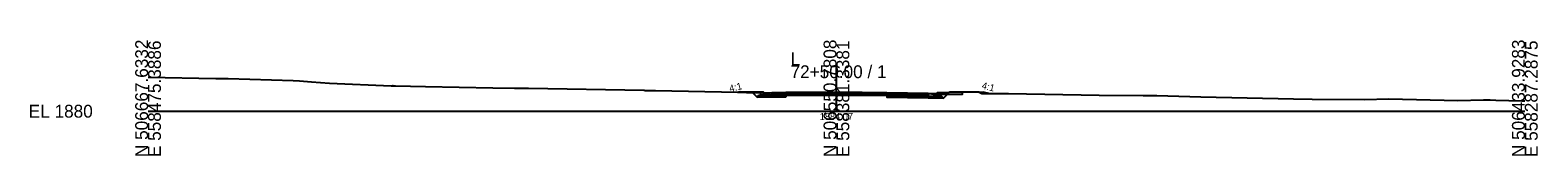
# Model space of a CAD drawing. Extents: x -26 to 4603, y -10 to 4703.
# Drawn here: x 2974.3 to 3302.8, y 1045.3 to 1070.4 of the extents above; entities that cross this region are included whole.
import ezdxf

# ---------------------------------------------------------------- set-up
doc = ezdxf.new("R2010")
doc.units = 0
for name, color, linetype in [('Default', 7, 'Continuous'), ('Exist Cross Section Cell', 7, 'Continuous'), ('Exist XS Ground Line', 7, 'Continuous'), ('Prop CMT Pvmt Course 1', 7, 'Continuous'), ('Prop CMT Pvmt Course 2', 7, 'Continuous'), ('Prop CMT Pvmt Course 3', 7, 'Continuous'), ('Prop CMT Pvmt Milling', 7, 'Continuous'), ('Prop CMT Shear Line', 7, 'Continuous'), ('Prop CMT Shld Paved Course 2', 7, 'Continuous'), ('Prop CMT Shld Paved Course 3', 7, 'Continuous'), ('Prop CMT Subgrade Earthwork', 7, 'Continuous'), ('Prop Conc 4in Sidewalk', 7, 'Continuous'), ('Prop Conc Curb and Gutter', 7, 'Continuous'), ('Prop Corridor Mesh Bottom', 7, 'Continuous'), ('Prop XS Finish Grade', 7, 'Continuous'), ('Prop XS Label Text', 7, 'Continuous'), ('Prop XS SS Elevation Text', 7, 'Continuous'), ('Scratch_Level_9', 7, 'Continuous')]:
    doc.layers.add(name, color=color, linetype=linetype)

msp = doc.modelspace()

# ---------------------------------------------------------------- linework, layer by layer
at = {"layer": 'Exist Cross Section Cell'}
for p, q in [((3150, 1055), (3150, 1065)), ((3000, 1055), (3150, 1055)), ((3150, 1055), (3300, 1055))]:
    msp.add_line(p, q, dxfattribs=at)
at = {"layer": 'Exist XS Ground Line'}
msp.add_lwpolyline([(3000, 1062.38), (3014.79, 1062.14), (3017.48, 1062.1), (3031.64, 1061.69), (3033, 1061.61), (3035.63, 1061.38), (3039.52, 1061.14), (3053, 1060.5), (3053.15, 1060.5), (3053.23, 1060.5), (3053.31, 1060.59), (3053.37, 1060.51), (3053.94, 1060.52), (3060.45, 1060.4), (3075.13, 1060.09), (3079.87, 1060.03), (3082.93, 1059.99), (3108.13, 1059.55), (3108.3, 1059.54), (3110.54, 1059.52), (3128.52, 1059.16), (3130.43, 1059.11), (3134.19, 1058.99), (3148.79, 1059.08), (3150.35, 1059.06), (3155.58, 1059.05), (3160.82, 1058.99), (3165.7, 1058.93), (3172.64, 1058.83), (3173.96, 1058.78), (3174.05, 1058.77), (3174.66, 1059.16), (3174.71, 1059.19), (3174.86, 1059.2), (3176.9, 1059.19), (3180.72, 1059.21), (3181.03, 1059.21), (3181.07, 1059.18), (3181.67, 1058.84), (3182.94, 1058.85), (3183.04, 1058.85), (3183.79, 1058.86), (3187.48, 1058.86), (3207.27, 1058.49), (3216.87, 1058.44), (3219.76, 1058.39), (3219.81, 1058.39), (3229.42, 1058.14), (3249.63, 1057.69), (3253.66, 1057.61), (3265.1, 1057.55), (3270.37, 1057.66), (3285.38, 1057.36), (3291.02, 1057.49), (3292.42, 1057.46), (3293.68, 1057.43), (3299.37, 1057.26), (3300, 1057.24)], dxfattribs=at)
at = {"layer": 'Prop CMT Pvmt Course 1'}
for points in [[(3136, 1059.1), (3139, 1059.1), (3139, 1058.85), (3139, 1058.85), (3136, 1058.85), (3136, 1058.85), (3136, 1058.85), (3136, 1059.1), (3136, 1059.1)], [(3150, 1059.1), (3148.79, 1059.08), (3148.79, 1059.08), (3139, 1059.1), (3139, 1059.1), (3139, 1058.85), (3139, 1058.85), (3139, 1058.85), (3148.79, 1058.83), (3148.79, 1058.83), (3150, 1058.85), (3150, 1058.85), (3150, 1058.85), (3150, 1059.1), (3150, 1059.1)], [(3161, 1058.98), (3150.35, 1059.1), (3150, 1059.1), (3150, 1058.85), (3150, 1058.85), (3150.35, 1058.85), (3161, 1058.73), (3161, 1058.73), (3161, 1058.98)], [(3161, 1058.98), (3161, 1058.98), (3161, 1058.73), (3161, 1058.73), (3161, 1058.73), (3169.96, 1058.62), (3169.96, 1058.62), (3169.96, 1058.87), (3161, 1058.98)]]:
    msp.add_lwpolyline(points, dxfattribs=at)
at = {"layer": 'Prop CMT Pvmt Course 2'}
for points in [[(3136, 1058.85), (3139, 1058.85), (3139, 1058.52), (3139, 1058.52), (3136, 1058.52), (3136, 1058.52), (3136, 1058.52), (3136, 1058.85), (3136, 1058.85)], [(3161, 1058.73), (3161, 1058.73), (3161, 1058.4), (3161, 1058.4), (3161, 1058.4), (3169.96, 1058.29), (3169.96, 1058.29), (3169.96, 1058.62), (3161, 1058.73)]]:
    msp.add_lwpolyline(points, dxfattribs=at)
at = {"layer": 'Prop CMT Pvmt Course 3'}
for points in [[(3136, 1058.52), (3139, 1058.52), (3139, 1058.15), (3139, 1058.15), (3136, 1058.15), (3136, 1058.15), (3136, 1058.15), (3136, 1058.52), (3136, 1058.52)], [(3161, 1058.4), (3161, 1058.4), (3161, 1058.03), (3161, 1058.03), (3161, 1058.03), (3169.96, 1057.91), (3169.96, 1057.91), (3169.96, 1058.29), (3161, 1058.47)], [(3169.96, 1058.29), (3169.96, 1058.29), (3169.96, 1057.91), (3169.96, 1057.91), (3169.96, 1057.91), (3173.35, 1057.84), (3173.35, 1057.84), (3172.97, 1058.23), (3169.96, 1058.29)]]:
    msp.add_lwpolyline(points, dxfattribs=at)
at = {"layer": 'Prop CMT Pvmt Milling'}
for points in [[(3150, 1059.07), (3148.79, 1059.08), (3148.79, 1059.08), (3139, 1059.02), (3139, 1059.02), (3139, 1058.98), (3139, 1058.98), (3139, 1058.98), (3148.79, 1058.96), (3148.79, 1058.96), (3150, 1058.98), (3150, 1058.98), (3150, 1058.98), (3150, 1059.07), (3150, 1059.07)], [(3161, 1058.98), (3155.58, 1059.05), (3150.35, 1059.06), (3150, 1059.07), (3150, 1058.98), (3150, 1058.98), (3150.35, 1058.97), (3161, 1058.86), (3161, 1058.86), (3161, 1058.86), (3161, 1058.86), (3161, 1058.98), (3161, 1058.98), (3161, 1058.98)]]:
    msp.add_lwpolyline(points, dxfattribs=at)
at = {"layer": 'Prop CMT Shld Paved Course 2'}
for points in [[(3150, 1058.85), (3148.79, 1058.83), (3148.79, 1058.83), (3139, 1058.85), (3139, 1058.85), (3139, 1058.52), (3139, 1058.52), (3139, 1058.52), (3148.79, 1058.5), (3148.79, 1058.5), (3150, 1058.52), (3150, 1058.52), (3150, 1058.52), (3150, 1058.85), (3150, 1058.85)], [(3161, 1058.73), (3150.35, 1058.85), (3150, 1058.85), (3150, 1058.52), (3150, 1058.52), (3150.35, 1058.51), (3161, 1058.4), (3161, 1058.4), (3161, 1058.4), (3161, 1058.4), (3161, 1058.73), (3161, 1058.73), (3161, 1058.73)]]:
    msp.add_lwpolyline(points, dxfattribs=at)
at = {"layer": 'Prop CMT Shld Paved Course 3'}
msp.add_lwpolyline([(3133, 1058.46), (3136, 1058.52), (3136, 1058.15), (3136, 1058.15), (3132.7, 1058.08), (3132.7, 1058.08), (3132.7, 1058.08), (3133, 1058.46), (3133, 1058.46)], dxfattribs=at)
at = {"layer": 'Prop CMT Subgrade Earthwork'}
msp.add_line((3132.7, 1058.08), (3136, 1058.15), dxfattribs=at)
for points in [[(3131.54, 1059.24), (3132.7, 1058.08), (3132.7, 1058.08)], [(3136, 1058.15), (3136, 1058.15), (3139, 1058.15)], [(3173.35, 1057.84), (3161, 1058.03), (3161, 1058.03)], [(3174.51, 1059.01), (3173.35, 1057.84), (3173.35, 1057.84)]]:
    msp.add_lwpolyline(points, dxfattribs=at)
at = {"layer": 'Prop Conc 4in Sidewalk'}
msp.add_lwpolyline([(3172.48, 1058.97), (3172.48, 1058.97), (3172.47, 1058.64), (3172.47, 1058.64), (3172.47, 1058.64), (3177.49, 1058.74), (3177.49, 1058.74), (3177.48, 1059.07), (3172.48, 1058.97)], dxfattribs=at)
at = {"layer": 'Prop Conc Curb and Gutter'}
for points in [[(3134, 1058.7), (3136, 1059.1), (3136, 1058.52), (3136, 1058.52), (3133.5, 1058.47), (3133.5, 1058.47), (3133.5, 1058.47), (3133.5, 1059.2), (3134, 1059.2), (3134, 1059.2), (3134, 1058.7), (3134, 1058.7), (3134, 1058.7)], [(3169.96, 1058.87), (3169.96, 1058.87), (3169.96, 1058.29), (3169.96, 1058.29), (3169.96, 1058.29), (3172.47, 1058.24), (3172.47, 1058.24), (3172.47, 1058.97), (3171.97, 1058.97), (3171.97, 1058.97), (3171.96, 1058.47), (3171.96, 1058.47), (3169.96, 1058.87)]]:
    msp.add_lwpolyline(points, dxfattribs=at)
at = {"layer": 'Prop Corridor Mesh Bottom'}
msp.add_lwpolyline([(3169.96, 1058.71), (3169.96, 1058.46)], dxfattribs=at)
at = {"layer": 'Prop XS Finish Grade'}
msp.add_line((3129, 1059.29), (3133.5, 1059.2), dxfattribs=at)
for points in [[(3128.46, 1059.16), (3129, 1059.29)], [(3172.48, 1058.97), (3172.47, 1058.97), (3172.47, 1058.97)], [(3181.97, 1059.16), (3177.48, 1059.07), (3177.48, 1059.07)], [(3183.2, 1058.85), (3181.97, 1059.16), (3181.97, 1059.16)]]:
    msp.add_lwpolyline(points, dxfattribs=at)
at = {"layer": 'Scratch_Level_9'}
msp.add_lwpolyline([(3136, 1058.82), (3136, 1058.57)], dxfattribs=at)

# ---------------------------------------------------------------- texts
at = {"layer": 'Default'}
msp.add_text('-', height=0.0001, dxfattribs=at).set_placement((3000, 1055))
at = {"layer": 'Exist Cross Section Cell'}
for s, p in [('N 506667.6332', (3000, 1045)), ('E 558475.3886', (3002.8, 1045)), ('N 506550.7808', (3150, 1045)), ('E 558381.3381', (3152.8, 1045)), ('N 506433.9283', (3300, 1045)), ('E 558287.2875', (3302.8, 1045))]:
    msp.add_text(s, height=2.8, rotation=90, dxfattribs=at).set_placement(p)
for s, p in [('L', (3140, 1065)), ('72+50.00 / 1', (3140, 1062.2)), ('EL 1880', (2974, 1053.6))]:
    msp.add_text(s, height=2.8, dxfattribs=at).set_placement(p)
at = {"layer": 'Prop CMT Shear Line'}
for p in [(3123.41, 1059.26), (3136, 1058.82), (3136, 1058.82), (3150, 1059.1), (3169.96, 1058.7), (3169.96, 1058.7), (3171.96, 1058.47), (3172.47, 1058.97), (3177.47, 1059.07), (3181.96, 1059.16), (3182.55, 1059.01)]:
    msp.add_text('X', height=0.0025, dxfattribs=at).set_placement(p)
at = {"layer": 'Prop XS Label Text'}
for rotation, p in [(14.0362, (3126.84, 1059.16)), (345.9638, (3181.57, 1059.94))]:
    msp.add_text('4:1', height=1.5, rotation=rotation, dxfattribs=at).set_placement(p)
at = {"layer": 'Prop XS SS Elevation Text'}
msp.add_text('1884.07', height=1.5, dxfattribs=at).set_placement((3146.36, 1053.09))

doc.saveas('drawing.dxf')
